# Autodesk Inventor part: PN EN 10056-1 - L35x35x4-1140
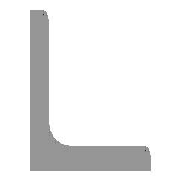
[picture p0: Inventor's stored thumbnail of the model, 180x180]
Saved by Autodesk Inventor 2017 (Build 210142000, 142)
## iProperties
Created: 2016-02
Part Number: PN EN 10056-1 - L35x35x4-1140
Material: Stal, miękka
Description: Kątownik równoramienny
Document SubType Name: Modeling
Standard: PN
Designer: X
Standards Organization: PN
Language: pl-PL
Size Designation: L35x35x4
Categories: <MemberInstance><Categories><Category DisplayName="Kształtowniki konstrukcyjne" InternalName="089c4875-fa83-4c05-b084-43b9cc11f5ed" Mnemonic="GRDR"><CategoryPar
Stock Number: L35x35x4
Density: 7.85 g/cm^3
Appearance: Częściowo polerowana
IsCustomPart: 1
_CCFamilyMember: 60
_CCFamilyDisplayName: PN EN 10056-1 (Kątownik równoramienny) - Kątownik równoramienny
_FrameMemberDoc: Frame Member File
_Version: 15.0.0
_GetPNFromCC: 1
Author: X
G_L: 1140,000 mm
G_W: 35,000 mm
G_H: 35,000 mm
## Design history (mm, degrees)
node "Płaszczyzna początkowa"
node "Płaszczyzna końcowa"
sketch "Szkic2"
  geometry: L1 (-6.019, -1.019)-(-6.019, 22.481); L2 (-10.019, 24.981)-(-8.519, 24.981); L3 (-10.019, -10.019)-(-10.019, 24.981); L4 (-10.019, -10.019)-(24.981, -10.019); L5 (24.981, -8.519)-(24.981, -10.019); L6 (-1.019, -6.019)-(22.481, -6.019); L7 (0, 28.185)-(0, -14.54) reference; L8 (-14.54, 0)-(28.185, 0) reference; A1 r 5 centre (-1.019, -1.019) between (-6.019, -1.019) and (-1.019, -6.019); A2 r 2.5 centre (-8.519, 22.481) between (-6.019, 22.481) and (-8.519, 24.981); A3 r 2.5 centre (22.481, -8.519) between (24.981, -8.519) and (22.481, -6.019); 3 further points
  constraints: 12 end point, 6 point on circle, 6 point on line, 6 tangent, 3 centre point, 3 horizontal, 3 vertical, 1 equal radius
  dimensions: "d4" = 35 distance of L3.start L4.end (= b); "d6" = 35 distance of L3.start L2.start (= b); "d8" = 4 distance of point (24.981, -6.019) L4.end (= ParT); "d10" = 4 distance of L2.start point (-6.019, 24.981) (= ParT); "d17" = 5 radius of A1 (= R); "d18" = 2.5 radius of A2 (= R1); "d19" = 10.01931 distance between parallel lines of L8 L4 (= ex); "d20" = 10.01931 distance between parallel lines of L3 L7 (= d19)
extrude "Bryła" new body sketch "Szkic2" stored distance "d11" = 1140 (= G_L); taper "d12" = 0 deg
node "Driven Length"
  sketch "Sketch3"
    geometry: L1 (0, 0)-(10, 0) reference
    constraints: 2 end point, 1 horizontal
  workplane "Work Plane10"
  sketch "Sketch4"
    geometry: L1 (-2, 0)-(12, 0) reference; L2 (-2, 1140)-(12, 1140) reference
    dimensions: "d24" = 1140 distance between parallel lines of L1 L2 (derived)
body "Solid1"
other parameters: "b" = 35 [user parameter; used in 3 equation terms], "ParT" = 4 [user parameter; used in 3 equation terms], "R" = 5 [user parameter; used in 1 equation term], "R1" = 2.5 [user parameter; used in 1 equation term], "G_L" = 1140 (= d24) [user parameter; used in 1 equation term], "d7" = 4 (derived), "d9" = 4 (derived), "ex" = 10.01931 (computed from b, ParT) [user parameter; used in 1 equation term], "G_OFFSET_START" = 0 [user parameter; used in 1 equation term], "G_OFFSET_END" = 0 [user parameter; used in 1 equation term], "d21" = 0 (computed from G_OFFSET_START), "d23" = 90 deg
